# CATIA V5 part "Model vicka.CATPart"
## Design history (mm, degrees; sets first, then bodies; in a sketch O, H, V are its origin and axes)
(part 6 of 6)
  Fillet141: radius 0.1, on edge [face of Pad16 from Sketch30.E8 | face of Chamfer14]; edge [face of Pad16 from Sketch30.E9 | face of Chamfer14]
  Fillet142: radius 0.1, on edge [face of Pad13 | face of Pad16 from Sketch30.E8]; edge [face of Pad13 | face of Pad16 from Sketch30.E9]
  Fillet143: radius 0.1, on edge [face of Chamfer14 | end face of Pad16]; edge [face of Pad16 from Sketch30.E18 | end face of Pad16]; edge [face of Pad16 from Sketch30.L4 | end face of Pad16]; edge [face of Chamfer35 | end face of Pad16]; edge [face of Pad16 from Sketch30.E12 | end face of Pad16]
  Chamfer36: length 5, angle 27.5, on edge [face of Pad18 from Sketch32.L1 | end face of Pad18]; edge [face of Pad18 from Sketch32.L2 | end face of Pad18]
  Fillet144: radius 0.5, on end face of Pad24
  Fillet145: radius 0.1, on edge [face of Pad25 | face of Pad25] (x8); edge [face of Pad25 | face of Pad24 from Sketch40.L12]; edge [face of Pad24 from Sketch40.L12 | face of Pad24 from Sketch40.L1]; edge [face of Pad24 from Sketch40.L1 | face of Pad24 from Sketch40.L2]; edge [face of Pad24 from Sketch40.L2 | face of Pad25]
  Fillet146: radius 0.2, on edge [face of Pad12 from Sketch20.E21 | face of Pad25]; edge [face of Pad13 | face of Pad25]
  Fillet147: radius 0.1, on edge [face of Pad25 | end face of Pocket8]
  Fillet148: radius 0.5, on edge [face of Pad12 from Sketch20.L3 | end face of Pocket10]
  Fillet149: radius 0.1, on edge [face of Pocket10 from Sketch29.E5 | face of Chamfer13]; edge [face of Pocket10 from Sketch29.E5 | end face of Pocket10]; edge [face of Pad12 from Sketch20.L3 | end face of Pocket8]
  Fillet150: radius 0.1, on edge [face of Pad13 | face of Pocket10 from Sketch29.E5]
  Fillet151: radius 0.1, on end face of Pad21
  Fillet152: radius 0.1, on edge [face of Pad13 | face of Pad21 from Sketch35.E8]
  Line4: type Tangency, RefPoint vertex [face of Rib2 | face of Rib2 | face of Pocket11], Curve edge [face of Pocket11 | face of Rib2], Start 0, End 0.083
  Line5: type PtPt, FirstPoint vertex of Line4, SecondPoint vertex [face of Rib2 | face of Rib2 | face of Pocket9 from Sketch27.L1 | face of Chamfer18 | end face of Pocket8]
  Fill4: Boundary (edge [face of Rib2 | face of Rib2]; Line4; Line5)
  SewSurface4: SplitPlane Fill4
  Fillet153: radius 0.1, on edge [end face of Pocket8 | face of Chamfer20]; edge [end face of Pocket8 | face of Chamfer18]
  Fillet154: radius 0.1, on edge [face of Pad13 from Sketch21.L2 | end face of Pocket8]
  Fillet155: radius 0.1, on edge [face of SewSurface4 | face of Pocket9 from Sketch27.L1]; edge [face of Pocket11 | face of Rib2]; edge [face of Pocket9 from Sketch27.L1 | face of Pocket11]
  Fillet156: radius 0.1, on edge [end face of Pocket8 | face of Pocket9 from Sketch27.L1]; edge [face of Pocket11 from Sketch38.L2 | face of Pocket11]
  Fillet157: radius 0.5, on edge [face of Chamfer18 | face of Pocket11 from Sketch38.L2]; edge [face of Pocket11 from Sketch38.L2 | face of Rib2]
  Fillet158: radius 0.5, on edge [face of Chamfer18 | end face of Pad20] (x2); edge [face of Chamfer19 | end face of Pad20]
  Fillet159: radius 0.5, on edge [face of Chamfer18 | face of Chamfer19]
  Fillet160: radius 0.5, on edge [face of Chamfer20 | face of Pad13]
  Fillet161: radius 0.5, on edge [face of Pad13 from Sketch21.L2 | face of Pad13]
  Fillet162: radius 0.1, on edge [face of Pad19 from Sketch33.E8 | end face of Pad20]; edge [face of Pad19 from Sketch33.E6 | end face of Pad20]
  Fillet163: radius 0.1, on edge [face of Pocket9 from Sketch27.E10 | face of Pocket11]; edge [face of Pocket9 | face of Pocket11]; edge [face of Pocket9 from Sketch27.E8 | face of Pocket11]
  Fillet164: radius 0.1, on edge [face of Pad11 | face of Pad14]; edge [face of Pad14 | face of Rib1]; edge [face of Chamfer7 | face of Pocket9 from Sketch27.E8]
  Fillet165: radius 0.5, on edge [face of Pad14 | end face of Pad14]
  Fillet166: radius 0.5, on edge [face of Chamfer6 | face of Pad14]; edge [face of Pad14 | face of Chamfer3]; edge [face of Chamfer3 | end face of Pad14]
  Fillet167: radius 0.5, on edge [face of Chamfer8 | face of Chamfer7]
  Fillet168: radius 0.5, on edge [face of Chamfer3 | end face of Pad14]; edge [face of Chamfer3 | face of Fillet166]
  Fillet169: radius 0.1, on edge [face of Pocket11 | face of Chamfer8]; edge [face of Pocket11 | face of Fillet167]; edge [face of Pocket11 | face of Chamfer10]; edge [face of Pocket11 | face of Chamfer9]
  Fillet170: radius 1, on edge [face of Shaft1 from Sketch57.L2 | face of Pad28 from Sketch60.A1]
  Fillet171: radius 1, on edge [face of Pad28 from Sketch60.A1 | end face of Pad28]
  Sketch131 on face of Pad30, origin (-16.699, 4.8982, 4.8982), H (0.2815, 0.9596, 0), V (0.26, -0.0763, 0.9626)
    projected circle E1 centre (31.0473, 28.8138) radius 1.75 from edge [face of Pad30 | face of Pad30 from Sketch63.A1]
  Pad50: profile Sketch131, direction (-0.9237, 0.2709, 0.2709), length 5
  Sketch132 on face of Pad50, origin (-21.3174, 6.2529, 6.2529), H (-0.2815, -0.9596, 0), V (0.26, -0.0763, 0.9626)
    projected arc E1 centre (-31.0463, 28.8148) radius 1.75 from (-29.2963, 28.8138) to (-29.3026, 28.9623) ccw from edge [face of Pad31 from Sketch64.A3 | face of Pad50]
    projected arc E2 centre (-31.0473, 28.8138) radius 1.75 from (-29.2973, 28.8138) to (-30.047, 30.2498) ccw from edge [face of Pad50 | face of Pad50 from Sketch131.E1]
    projected arc E3 centre (-31.0473, 28.8138) radius 1.75 from (-29.2973, 28.8138) to (-29.3038, 28.9644) ccw from edge [face of Pad50 | face of Pad50 from Sketch131.E1]
    line L1 (-29.3026, 28.9623) -> (-29.3038, 28.9644)
  Pad51: profile Sketch132, direction (0.9237, -0.2709, -0.2709), length 5
  Sketch133 on end face of Pad30, origin (-18.5463, 5.4401, 5.4401), H (-0.2815, -0.9596, 0), V (0.26, -0.0763, 0.9626)
  Pad52: profile Sketch133, direction (-0.9237, 0.2709, 0.2709), length 3.2
  Sketch134 on end face of Pad30, origin (-18.5463, 5.4401, 5.4401), H (-0.2815, -0.9596, 0), V (0.26, -0.0763, 0.9626)
  Pad53: profile Sketch134, direction (-0.9237, 0.2709, 0.2709), length 3.2
  Sketch135 on end face of Pad30, origin (-18.5463, 5.4401, 5.4401), H (-0.2815, -0.9596, 0), V (0.26, -0.0763, 0.9626)
  Pad54: profile Sketch135, direction (-0.9237, 0.2709, 0.2709), length 3.2
  Fillet172: radius 0.7, on edge [face of Pad52 | end face of Pad52]; edge [face of Pad53 | end face of Pad53]; edge [face of Pad54 | end face of Pad54]
  Fillet173: radius 0.1, on edge [face of Pad53 | face of Fillet172] (x2); edge [face of Pad53 | face of Pad51] (x2); edge [face of Pad53 | face of Pad53] (x2); edge [face of Pad51 | face of Pad53]; edge [face of Pad53 | end face of Pad53]
  Fillet174: radius 0.1, on face of Pad54 (x3)
  Fillet175: radius 0.1, on edge [face of Pad52 | face of Fillet172] (x2); edge [face of Pad52 | end face of Pad52]
  Fillet176: radius 0.1, on edge [face of Pad51 | face of Pad52] (x2); edge [face of Pad52 | face of Pad52]
  Fillet177: radius 1, on edge [face of Shaft1 from Sketch57.L3 | face of Shaft1 from Sketch57.L2]
  Fillet178: radius 0.1, on edge [face of Shaft1 from Sketch57.L2 | face of Chamfer6]
  Fillet179: radius 0.5, on end face of Pad22
  Fillet180: radius 0.1, on edge [face of Pad23 | face of Pad23]
  Sketch136 on end face of Pocket8, origin (-0.8, 0, 0), H (0, -1, 0), V (0, 0, 1)
  Pad55: profile Sketch136, direction (-1, 0, 0), length 2.5
  Fillet181: radius 0.1, on edge [face of Pad12 from Sketch20.E36 | face of Pad23]
  Fillet182: radius 0.1, on edge [face of Pad23 | end face of Pocket8] (x2)
  Fillet183: radius 0.1, on edge [face of Pad23 | face of Pad22]
  Fillet184: radius 0.1, on edge [face of Pad23 | end face of Pad55]; edge [face of Pad22 | end face of Pad55]; edge [end face of Pad55 | face of Fillet15]
  Fillet185: radius 0.1, on edge [face of Pad23 | face of Pad22 from Sketch39.L2]; edge [face of Pad13 | face of Pad23]
  Fillet186: radius 0.1, on edge [face of Pad22 from Sketch39.L2 | face of Pad13]; edge [face of Pad13 | face of Pad23]
  Fillet187: radius 0.1, on edge [face of Pad22 from Sketch39.L2 | face of Pad23]; edge [face of Pad23 | face of Pad23]; edge [face of Pad23 | end face of Pocket8]
  Fillet188: radius 0.1, on edge [face of Pad23 | end face of Pocket8] (x3); edge [face of Pad23 | face of Pad23] (x2)
  Fillet189: radius 3, on edge [face of Pad11 from Sketch19.L12 | face of Pad11 from Sketch19.L13]
  Fillet190: radius 0.1, on edge [face of Pad15 from Sketch28.L1 | face of Pad13]
  Fillet191: radius 0.1, on edge [end face of Pocket8 | face of Pad12 from Sketch20.E34]; edge [end face of Pocket8 | face of Pad12 from Sketch20.E32]; edge [end face of Pocket8 | face of Pad12 from Sketch20.L1]; edge [end face of Pocket8 | face of Pad12]
  Fillet192: radius 0.1, on edge [end face of Pocket8 | face of Pad12 from Sketch20.E25]
  Fillet193: radius 0.1, on end face of Pocket19 (x3); edge [end face of Pad10 | face of Pocket19 from Sketch67.L10]; edge [end face of Pad10 | face of Pocket19 from Sketch67.L6]; edge [end face of Pad10 | face of Pocket19 from Sketch67.L2]
  Fillet194: radius 0.1, on edge [end face of Pad10 | face of Pocket23 from Sketch71.E12]; end face of Pocket23 (x2); edge [end face of Pad10 | face of Pocket23 from Sketch71.L4]
  Fillet195: radius 0.1, on edge [end face of Pad10 | face of Pocket27 from Sketch75.E10]; end face of Pocket27 (x3); edge [end face of Pad10 | face of Pocket27 from Sketch75.L10]; edge [end face of Pad10 | face of Pocket27 from Sketch75.L4]
  Fillet196: radius 0.1, on edge [face of Pad21 from Sketch35.E8 | face of Chamfer17]
  Fillet197: radius 0.1, on edge [face of Hole2 | face of Hole2]
  Fillet198: radius 0.1, on edge [face of Pad21 from Sketch35.E10 | face of Chamfer17]; edge [face of Pad21 from Sketch35.E5 | face of Chamfer17]
  Fillet199: radius 0.1, on edge [face of Slot4 | face of Slot4]
  Fillet200: radius 0.1, on edge [face of Pad47 from Sketch118.L2 | face of Slot4]
  Fillet201: radius 0.1, on edge [face of Slot4 | face of Pocket46]; edge [face of Slot4 | face of Pad47 from Sketch118.L2]
  Fillet202: radius 0.1, on end face of Pocket38; edge [face of Pocket38 from Sketch119.L12 | face of Pocket38 from Sketch119.L17]
  Fillet203: radius 0.1, on edge [face of Chamfer6 | end face of Pocket8]; edge [face of Chamfer9 | face of Pocket9 from Sketch27.L2]; edge [end face of Pocket8 | face of Pocket9 from Sketch27.L2]
  Fillet204: radius 0.1, on edge [end face of Pad14 | face of Rib1]; edge [face of Rib1 | end face of Pad14] (x5); edge [face of Rib1 | face of Chamfer4] (x2); edge [face of Rib1 | face of Pad13]
  Fillet205: radius 0.1, on edge [face of Fillet189 | face of Rib1]
  Fillet206: radius 0.1, on edge [face of Pad11 from Sketch19.C10 | face of Pad13]
  Fillet207: radius 0.1, on edge [face of Pocket40 from Sketch121.A17 | end face of Pocket40]
  Fillet208: radius 0.1, on edge [face of Pocket40 from Sketch121.A3 | end face of Pocket40]
  Fillet209: radius 0.1, on edge [face of Pad26 from Sketch41.L2 | face of Pad26 from Sketch41.L3]; edge [face of Fillet17 | face of Fillet17] (x3)
  Fillet210: radius 0.1, on edge [face of Pocket8 from Sketch18.A2 | face of Pocket8 from Sketch18.A1]
  Fillet211: radius 0.1, on edge [face of Pad13 | face of Chamfer19]
  Fillet212: radius 0.1, on edge [face of Pad11 from Sketch19.L2 | face of Pad11 from Sketch19.L3]; edge [face of Pad19 from Sketch33.E5 | face of Pad19 from Sketch33.L3]; edge [face of Pad19 from Sketch33.L3 | face of Pad19 from Sketch33.E3]
  Fillet213: radius 0.1, on edge [face of Rib1 | face of Fillet206]
  Fillet214: radius 0.1, on edge [face of Pad13 | face of Chamfer4]
  Fillet215: radius 0.6, on edge [face of Slot2 | face of Slot2]
  Fillet216: radius 0.1, on edge [face of Slot2 | face of Chamfer27] (x2); edge [face of Slot2 | face of Pad32 from Sketch83.L6] (x2)
  Fillet217: radius 0.1, on edge [face of Chamfer27 | face of Pocket46]
  Fillet218: radius 0.1, on edge [face of Slot2 | face of Pocket46]; edge [face of Pocket46 | face of Slot2] (x2); edge [face of Pad32 from Sketch83.L5 | face of Pocket46]; edge [face of Pad32 from Sketch83.L5 | face of Slot2]; face of Slot2
  Chamfer37: length 3.8, second length 0.2, on edge [face of Pad10 from Sketch17.A26 | end face of Pad10]
  Fillet219: radius 0.1, on end face of Pocket25; edge [end face of Pad10 | face of Pocket25 from Sketch73.L1]; edge [end face of Pad10 | face of Pocket25 from Sketch73.E2]
  Chamfer38: length 3.8, second length 0.2, on edge [face of Pad10 | end face of Pad10]; edge [face of Pad10 from Sketch17.A22 | end face of Pad10]; edge [face of Pad10 from Sketch17.L8 | end face of Pad10]
  Fillet220: radius 0.1, on end face of Pocket24 (x3); edge [end face of Pad10 | face of Pocket24 from Sketch72.E13]; edge [end face of Pad10 | face of Pocket24 from Sketch72.L1]; edge [end face of Pad10 | face of Pocket24 from Sketch72.L2]
  Chamfer39: length 2.2, second length 0.2, on edge [face of Chamfer25 | end face of Pad10]
  Chamfer40: length 3.8, second length 0.2, on edge [face of Pad10 | end face of Pad10]; edge [face of Pocket30 | end face of Pad10]
  Chamfer41: length 3.8, second length 0.2, on edge [face of Pad10 from Sketch17.L2 | end face of Pad10]
  Chamfer42: length 3.8, second length 0.2, on edge [face of Pad10 from Sketch17.A14 | end face of Pad10]; edge [face of Pad10 | end face of Pad10]; edge [face of Chamfer37 | end face of Pad10]
  Chamfer43: length 3.8, second length 0.2, on edge [face of Pad10 from Sketch17.L6 | end face of Pad10]
  Chamfer44: length 0.2, second length 3.8, on edge [end face of Pad10 | face of Pocket45]
  Chamfer45: length 3.8, second length 0.2, on edge [face of Pocket44 | end face of Pad10]
  Chamfer46: length 0.2, second length 2, on edge [end face of Pad10 | face of Hole1]
  Chamfer47: length 0.2, second length 2, on edge [end face of Pad10 | face of Hole6]
  Chamfer48: length 0.2, second length 2, on edge [end face of Pad10 | face of Hole2]
  Chamfer49: length 0.2, second length 2, on edge [end face of Pad10 | face of Hole3]
  Chamfer50: length 0.2, second length 2, on edge [end face of Pad10 | face of Hole4]
  Chamfer51: length 0.2, second length 2, on edge [end face of Pad10 | face of Hole5]
  Chamfer52: length 0.2, second length 3, on edge [end face of Pad10 | face of Pocket8 from Sketch18.A4]
  Chamfer53: length 0.2, second length 3, on edge [end face of Pad10 | face of Pocket8 from Sketch18.A12]; edge [end face of Pad10 | face of Pocket8 from Sketch18.A13]; edge [end face of Pad10 | face of Pocket8 from Sketch18.A10]; edge [end face of Pad10 | face of Pocket8 from Sketch18.A8]; edge [end face of Pad10 | face of Pocket8 from Sketch18.A6]
  Chamfer54: length 0.2, second length 3, on edge [end face of Pad10 | face of Pocket8 from Sketch18.A14]; edge [end face of Pad10 | face of Pocket8 from Sketch18.A15]; edge [end face of Pad10 | face of Pocket8 from Sketch18.A16]; edge [end face of Pad10 | face of Pocket8 from Sketch18.A17]; edge [end face of Pad10 | face of Pocket8 from Sketch18.A18]
  Chamfer55: length 0.2, second length 3, on edge [end face of Pad10 | face of Pocket8 from Sketch18.L3]; edge [end face of Pad10 | face of Pocket8 from Sketch18.A19]
  Chamfer56: length 0.2, second length 1.5, on edge [face of Pad9 | face of Pad1 from Sketch1.A1]
  Chamfer57: length 0.2, second length 1.5, on edge [face of Pad9 | face of Pad1 from Sketch1.A1]
  Chamfer58: length 0.2, second length 1.5, on edge [face of Pad9 | face of Pad1 from Sketch1.A1]
  Chamfer59: length 0.2, second length 1.5, on edge [face of Pad6 from Sketch12.L1 | face of Pad9]
  Chamfer60: length 0.2, second length 1.5, on edge [face of Pocket21 | face of Pocket5 from Sketch10.A2]; edge [face of Pocket21 | face of Pad1 from Sketch1.A1]; edge [face of Pocket21 | face of Pocket5 from Sketch10.L1]
  Chamfer61: length 0.2, second length 1.5, on edge [face of Pocket21 | face of Pocket6 from Sketch11.A1]; edge [face of Pocket1 from Sketch2.A2 | face of Pocket21]
  Chamfer62: length 0.2, second length 1.5, on edge [face of Pocket3 | face of Pocket21]
  Chamfer63: length 0.2, second length 1.5, on edge [face of Pad9 | face of Pad1 from Sketch1.A1] (x2)
  Fillet221: radius 0.1, on face of Hole5; edge [end face of Pad10 | face of Chamfer51]
  Fillet222: radius 0.1, on end face of Pocket26; edge [end face of Pad10 | face of Pocket26 from Sketch74.E7]
  Fillet223: radius 0.1, on end face of Pocket26; edge [end face of Pad10 | face of Pocket26 from Sketch74.E4]; edge [end face of Pad10 | face of Pocket26 from Sketch74.L1]
  Fillet224: radius 0.1, on edge [face of Chamfer42 | end face of Pad10] (x2); edge [face of Pad9 | face of Chamfer57]
  Fillet225: radius 0.1, on face of Hole4; edge [end face of Pad10 | face of Chamfer50]; end face of Pocket25 (x2); edge [end face of Pad10 | face of Pocket25 from Sketch73.L4]; edge [end face of Pad10 | face of Pocket25 from Sketch73.E16]; edge [end face of Pad10 | face of Chamfer38]
  Fillet226: radius 0.1, on edge [end face of Pad10 | face of Chamfer49]; edge [face of Pad10 | face of Chamfer40]
  Fillet227: radius 0.1, on edge [end face of Pocket30 | face of Chamfer59]; edge [face of Chamfer58 | end face of Pocket30]; edge [face of Chamfer58 | face of Chamfer59]
  Fillet228: radius 0.1, on edge [face of Pocket30 | face of Pocket30 from Sketch78.A1]
  Fillet229: radius 0.1, on edge [face of Chamfer59 | face of Pocket30 from Sketch78.A1]
  Fillet230: radius 0.1, on edge [face of Chamfer39 | face of Chamfer40]; end face of Pocket22; edge [face of Chamfer39 | end face of Pad10]; edge [face of Chamfer39 | face of Chamfer48]; edge [face of Fillet26 | face of Chamfer39]
  Fillet231: radius 0.1, on edge [face of Chamfer39 | face of Hole2]; edge [face of Chamfer39 | face of Chamfer48]
  Fillet232: radius 0.1, on edge [face of Chamfer39 | end face of Pad10]; edge [face of Chamfer40 | end face of Pad10]
  Fillet233: radius 0.1, on edge [face of Pocket30 | face of Pocket30]
  Fillet234: radius 0.1, on edge [face of Chamfer40 | end face of Pad10]
  Fillet235: radius 0.1, on edge [face of Pocket21 | face of Chamfer40]; edge [face of Pocket21 | face of Pocket21 from Sketch69.L3]; edge [face of Pocket21 | end face of Pocket21]; edge [face of Pocket21 from Sketch69.L3 | end face of Pocket21]; edge [face of Pocket21 from Sketch69.L3 | face of Chamfer40]
  Fillet236: radius 0.1, on edge [end face of Pocket20 | end face of Pocket21]
  Fillet237: radius 0.1, on edge [face of Pocket20 from Sketch68.L2 | end face of Pocket20]; edge [face of Pocket20 from Sketch68.L2 | face of Pocket21 from Sketch69.L3]
  Fillet238: radius 0.1, on edge [face of Pocket21 | face of Chamfer41]; edge [face of Pocket21 from Sketch69.L1 | face of Pocket21]
  Fillet239: radius 0.1, on edge [face of Pocket21 from Sketch69.L1 | face of Chamfer41]; edge [face of Pocket20 from Sketch68.L1 | face of Pocket21 from Sketch69.L1]; edge [face of Pocket20 from Sketch68.L1 | face of Chamfer41]; edge [end face of Pad10 | face of Pocket20 from Sketch68.L1]
  Fillet240: radius 0.1, on edge [end face of Pad10 | face of Pocket20 from Sketch68.L2]; edge [face of Pocket20 from Sketch68.L2 | face of Chamfer55]; edge [end face of Pad10 | face of Chamfer55]; edge [face of Pocket17 from Sketch65.L2 | face of Chamfer41]; edge [end face of Pad10 | face of Pocket17 from Sketch65.L2]; edge [face of Pocket17 from Sketch65.L2 | face of Pocket17]; edge [face of Pocket17 from Sketch65.L2 | face of Chamfer55]
  Fillet241: radius 0.1, on edge [face of Pocket17 | face of Chamfer43]; edge [face of Chamfer55 | face of Pocket17]; edge [face of Pocket17 | face of Chamfer52]
  Fillet242: radius 0.1, on edge [face of Chamfer52 | face of Pocket17 from Sketch65.L1]; edge [face of Pocket17 from Sketch65.L1 | face of Pocket17] (x2); face of Pocket17 from Sketch65.L1; edge [end face of Pad10 | face of Chamfer46]; edge [face of Chamfer46 | face of Pocket17]; edge [face of Chamfer43 | end face of Pad10]; edge [end face of Pad10 | face of Pocket17 from Sketch65.L1]; edge [face of Chamfer43 | face of Pocket17 from Sketch65.L1]; edge [face of Pocket17 from Sketch65.L1 | face of Chamfer46]
  Fillet243: radius 0.1, on edge [end face of Pad10 | face of Chamfer47]; edge [face of Chamfer47 | face of Hole6]; edge [face of Hole6 | face of Hole6]; edge [face of Chamfer43 | face of Chamfer44]; edge [face of Chamfer45 | end face of Pad10] (x2); edge [end face of Pad10 | face of Pad2]
  Fillet244: radius 0.1, on edge [face of Pocket21 | face of Chamfer43]
  Fillet245: radius 0.1, on edge [face of Chamfer61 | face of Pocket21]
  Fillet246: radius 0.1, on edge [face of Chamfer62 | face of Pocket21]
  Fillet247: radius 0.1, on edge [face of Pocket3 | face of Pad9]; edge [face of Pad5 from Sketch7.A1 | face of Pad9]; edge [face of Pocket3 | face of Pad5 from Sketch7.A1]; edge [face of Pocket3 | face of Chamfer43]
  Fillet248: radius 0.1, on edge [face of Pad9 | face of Chamfer56] (x2)
  Fillet249: radius 0.1, on edge [face of Pocket44 | face of Chamfer45]
  Fillet250: radius 0.2, on edge [face of Pad9 | face of Chamfer45]
  Fillet251: radius 0.1, on edge [face of Chamfer37 | face of Chamfer42]
  Fillet252: radius 0.1, on edge [face of Chamfer38 | face of Pad9] (x2); edge [face of Pad9 | face of Chamfer63] (x2); edge [face of Pocket29 from Sketch77.A1 | face of Pad9]; edge [face of Pocket29 | end face of Pocket29]; edge [end face of Pocket29 | face of Chamfer63]; edge [face of Pocket29 from Sketch77.A1 | face of Chamfer63]; edge [face of Pocket29 | face of Chamfer63]; edge [face of Pocket29 | face of Pad9]
  Fillet253: radius 0.1, on edge [face of Pad9 | face of Chamfer40]
  Fillet254: radius 0.1, on edge [end face of Pad10 | face of Pocket29]
  Fillet255: radius 0.1, on edge [face of Pad9 | face of Chamfer58] (x2)
  Fillet256: radius 0.1, on edge [face of Chamfer58 | face of Pocket30 from Sketch78.A1]
  Fillet257: radius 0.1, on edge [face of Pocket30 from Sketch78.A1 | end face of Pocket30]; edge [face of Pocket30 from Sketch78.A1 | face of Pocket30]; edge [face of Pocket30 | end face of Pocket30]
  Fillet258: radius 0.1, on edge [face of Pad9 | face of Pocket30 from Sketch78.A1]
  Fillet259: radius 0.1, on edge [face of Pocket21 | face of Chamfer60]
  Fillet260: radius 0.1, on edge [face of Chamfer60 | face of Chamfer61]
  Fillet261: radius 0.2, on edge [face of Pocket21 | face of Chamfer61]; edge [face of Pocket21 | face of Chamfer60] (x2)
  Fillet262: radius 0.1, on edge [face of Pocket21 | face of Chamfer43]
  Fillet263: radius 0.1, on edge [face of Pocket21 | face of Chamfer43]
  Fillet264: radius 0.1, on edge [end face of Pad10 | face of Chamfer52]; edge [end face of Pad10 | face of Pocket28 from Sketch76.L1]; edge [face of Pocket28 from Sketch76.L1 | face of Chamfer52]; face of Pocket28 from Sketch76.L1
  Fillet265: radius 0.1, on edge [face of Chamfer45 | end face of Pocket28]; edge [face of Chamfer52 | end face of Pocket28]; edge [face of Pocket28 from Sketch76.L2 | end face of Pocket28]; edge [end face of Pad10 | face of Pocket28 from Sketch76.L2]
  Fillet266: radius 0.1, on edge [face of Pocket28 from Sketch76.L2 | face of Chamfer53]
  Fillet267: radius 0.1, on edge [end face of Pad10 | face of Chamfer53] (x4); edge [end face of Pad10 | face of Chamfer54] (x5)
  Fillet268: radius 0.1, on edge [face of Chamfer54 | end face of Pocket8] (x5); edge [face of Chamfer53 | end face of Pocket8] (x5); edge [face of Chamfer52 | end face of Pocket8]; edge [face of Chamfer55 | end face of Pocket8]
  Fillet269: radius 0.1, on edge [end face of Pocket18 | face of Chamfer41]; edge [face of Pocket18 from Sketch66.L2 | face of Chamfer41]; edge [face of Pocket18 from Sketch66.L2 | face of Pocket18 from Sketch66.E6]; edge [face of Pocket18 from Sketch66.E6 | end face of Pocket18]; edge [face of Pocket18 from Sketch66.L2 | end face of Pocket18]; edge [face of Pocket17 | face of Pocket18 from Sketch66.E6]; edge [face of Pocket17 | face of Pocket18 from Sketch66.L2]; edge [face of Chamfer41 | face of Pocket17]; edge [face of Chamfer41 | end face of Pad10]; edge [face of Pocket17 | face of Pocket18 from Sketch66.L1]
  Chamfer64: length 0.2, second length 3, on edge [face of Pad11 from Sketch19.C5 | face of Pad13]
  Chamfer65: length 0.2, second length 3, on edge [face of Pad19 | face of Pad13]
  Chamfer66: length 0.2, second length 3, on edge [face of Pad11 from Sketch19.C19 | face of Pad13]
  Chamfer67: length 0.2, second length 3, on edge [face of Pad11 from Sketch19.C17 | face of Pad13]
  Chamfer68: length 0.2, second length 3, on edge [face of Pad11 from Sketch19.C12 | face of Pad13]
  Fillet270: radius 0.1, on edge [face of Pad16 from Sketch30.E3 | end face of Pad16]; edge [face of Pad16 from Sketch30.E6 | end face of Pad16]; edge [face of Chamfer67 | face of Chamfer15]; edge [end face of Pad16 | face of Chamfer67]; edge [face of Chamfer15 | end face of Pad16]; edge [face of Pad16 from Sketch30.E12 | face of Chamfer15]
  Fillet271: radius 0.1, on edge [face of Chamfer66 | face of Pad13]
  Fillet272: radius 0.1, on edge [face of Pad18 from Sketch32.E6 | face of Pad18 from Sketch32.E8]
  Fillet273: radius 0.1, on edge [face of Pad18 from Sketch32.E8 | face of Chamfer36]
  Fillet274: radius 0.1, on edge [face of Pad18 from Sketch32.E8 | face of Chamfer36]
  Fillet275: radius 0.2, on edge [face of Chamfer12 | face of Pad13]; edge [face of Chamfer12 | end face of Pad15]; edge [face of Pad15 from Sketch28.L1 | face of Chamfer12]; edge [face of Pad15 | face of Chamfer12]
  Fillet276: radius 0.2, on edge [face of Chamfer11 | end face of Pad15]; edge [face of Pad15 | end face of Pad15]; edge [face of Pad15 | face of Chamfer11]; face of Chamfer11
  Fillet277: radius 0.2, on edge [face of Pad15 from Sketch28.L1 | end face of Pad15]
  Fillet278: radius 0.2, on edge [face of Chamfer2 | face of Fillet189]; edge [face of Rib1 | face of Chamfer2]
  Fillet279: radius 0.2, on edge [face of Pad11 from Sketch19.C11 | face of Pad13]
  Fillet280: radius 0.2, on edge [face of Chamfer68 | face of Pad13]; edge [face of Pad15 | face of Pad13]
  Fillet281: radius 0.2, on edge [face of Rib1 | face of Rib1] (x6); edge [face of Chamfer2 | face of Rib1]; edge [face of Rib1 | face of Chamfer2]
  Fillet282: radius 0.1, on edge [face of Pad19 from Sketch33.E3 | end face of Pad19]
  Fillet283: radius 0.1, on edge [face of Pad19 from Sketch33.E8 | end face of Pad19]
  Fillet284: radius 0.1, on edge [end face of Pad19 | face of Pad19 from Sketch33.E6]
  Fillet285: radius 0.1, on edge [face of Chamfer22 | end face of Pad19]
  Fillet286: radius 0.1, on face of Chamfer21
  Fillet287: radius 0.1, on edge [face of Chamfer65 | face of Pad13]; edge [face of Pad13 | face of Pocket9] (x2); edge [face of Chamfer64 | face of Pad13]; edge [face of Pad11 from Sketch19.L7 | face of Pad13]
  Fillet288: radius 0.1, on edge [face of Rib1 | face of Chamfer1]; edge [face of Rib1 | face of Rib1] (x4)
  Fillet289: radius 0.1, on edge [face of Pad11 from Sketch19.C1 | face of Pad13]; edge [face of Pad18 from Sketch32.E4 | face of Chamfer36]; edge [face of Pad18 from Sketch32.E2 | face of Chamfer36]
  Fillet290: radius 0.1, on edge [face of Pad13 | face of Chamfer36]
  Fillet291: radius 0.1, on end face of Pad18
  Fillet292: radius 0.5, on edge [face of Pad18 from Sketch32.E2 | face of Chamfer36]
  Fillet293: radius 0.1, on edge [face of Pad21 from Sketch35.E3 | face of Chamfer17]
  Plane12: type Offset, RefPlane xy-plane, Offset -46
  Sketch137 on Plane12, origin (0, 0, -46), H (1, 0, 0), V (0, 1, 0)
    point P1 (-1.8, -9)
    line L1 (-0.8, -6.5) -> (-0.8, -11.5)
    line L2 (-0.8, -11.5) -> (-2.8, -11.5)
    line L3 (-2.8, -11.5) -> (-2.8, -6.5)
    point P6 (-1.8, 0)
    line L4 (-0.8, 2.5) -> (-0.8, -2.5)
    line L5 (-2.8, -2.5) -> (-2.8, 2.5)
    point P7 (-0.8, 2.5)
    point P11 (-1.8, 9)
    line L6 (-0.8, 11.5) -> (-0.8, 6.5)
    line L7 (-2.8, 6.5) -> (-2.8, 11.5)
    line L8 (-2.8, 11.5) -> (-0.8, 11.5)
    reference projected line E1 (1.6, 12.2188) -> (1.6, -13.716) from edge [face of Pocket46 | face of Fillet106]
    line L9 (-2.8, -6.5) -> (-2.8, -2.5)
    line L10 (-2.8, 2.5) -> (-2.8, 6.5)
    line L11 (-0.8, 2.5) -> (-0.8, 6.5)
    line L12 (-0.8, -2.5) -> (-0.8, -6.5)
    reference projected point E2 (1.5, 68.6438) from vertex [face of Chamfer58 | face of Fillet116 | face of Chamfer58 | face of Fillet116]
    length L5 = 5
    length L8 = 2
    length L7 = 5
    distance L6 E1 = 2.4
    distance L8 E2 = 57.1438
    distance L2 L8 = 23
    vertical: L1 V, L3 V, L4 V, L5 V, L6 V, L7 V, L9 V, L10 V, L11 V, L12 V
    horizontal: L2 H, L8 H
    equidistance: L1 L3 P1, L4 L5 P6, L6 L7 P11
    coincidence: P6 H, P7 L1
  Pocket48: profile Sketch137, direction (0, 0, 1), length 4
  Fillet294: radius 0.5, on edge [face of Pocket48 | face of Pocket48 from Sketch137.L8]
  Fillet295: radius 0.5, on edge [face of Pocket48 from Sketch137.L8 | face of Pocket48 from Sketch137.L7]; edge [face of Pocket48 from Sketch137.L3 | face of Pocket48 from Sketch137.L2]; edge [face of Pocket48 from Sketch137.L2 | face of Pocket48]
  Fillet296: radius 0.5, on edge [face of Pocket48 | face of Chamfer43]
  Plane13: type Offset, RefPlane yz-plane, Offset 1.6
  Sketch138 on Plane13, origin (1.6, 0, 0), H (0, 1, 0), V (0, 0, 1)
    line L1 (-102.0887, 0) -> (101.0793, 0)
    point P1 (-102.0887, 0)
    coincidence: P1 H
    horizontal: L1 H
  Extrude1: Element1 Sketch138, Lim1 100, Lim2 100, Direction (0, 0, 1)
  Plane14: type Offset, RefPlane xy-plane, Offset 43.5, reversed
  Sketch139 on Plane14, origin (0, 0, -43.5), H (1, 0, 0), V (0, 1, 0)
    line L1 (0, -102.0887) -> (0, 101.0793)
    point P1 (0, -102.0887)
    point P2 (0, 101.0793)
    reference projected point E1 (1.6, 101.0793) from vertex [face of Extrude1 from Sketch138.L1]
    reference projected point E2 (1.6, -102.0887) from vertex [face of Extrude1 from Sketch138.L1]
    distance E1 P2 V = 0
    distance P1 E2 V = 0
    coincidence: P1 V
    vertical: L1 V
  Extrude2: Element1 Sketch139, Lim1 100, Lim2 100, Direction (1, 0, 0)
